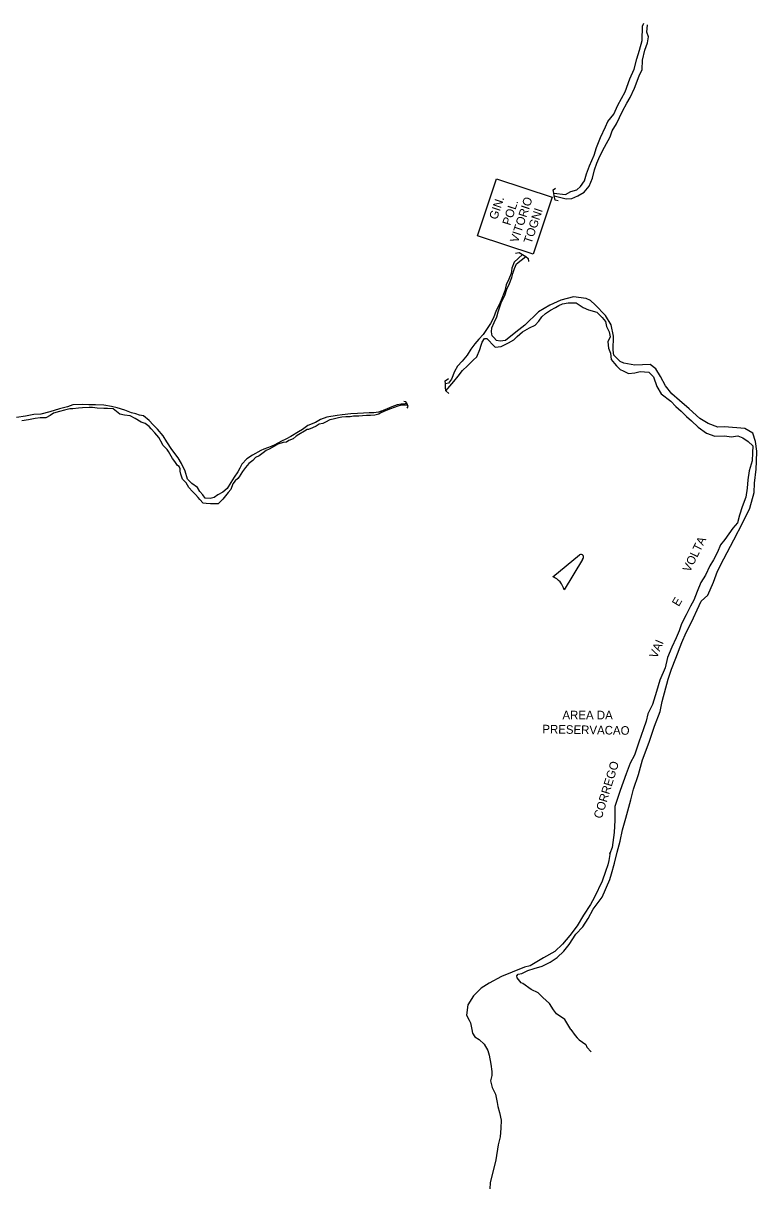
# Model space of a CAD drawing. Extents: x 325899 to 363134, y 7578590 to 7592502.
# Drawn here: x 337514 to 337857, y 7587928 to 7588472 of the extents above; entities that cross this region are included whole.
import ezdxf

# ---------------------------------------------------------------- set-up
doc = ezdxf.new("R2010")
doc.units = 0
for name, color, linetype in [('EDIFEXISTENT', 7, 'Continuous'), ('EDIFIDENTIF', 7, 'Continuous'), ('EDIFOBRAEXIS', 7, 'Continuous')]:
    doc.layers.add(name, color=color, linetype=linetype)

msp = doc.modelspace()

# ---------------------------------------------------------------- linework, layer by layer
at = {"layer": 'EDIFEXISTENT'}
for p, q in [((337726.34, 7588372.59), (337735.22, 7588399.29)), ((337735.22, 7588399.29), (337761.07, 7588390.69)), ((337761.07, 7588390.69), (337752.23, 7588364.13)), ((337761.63, 7588394.08), (337762.66, 7588394.92)), ((337761.9, 7588392.59), (337761.63, 7588394.08)), ((337762.11, 7588391.28), (337761.9, 7588392.59)), ((337762.58, 7588389.34), (337762.11, 7588391.28)), ((337763.93, 7588388.98), (337762.58, 7588389.34)), ((337752.23, 7588364.13), (337726.34, 7588372.59)), ((337744.09, 7588364.52), (337745.79, 7588364.89)), ((337745.79, 7588364.89), (337747.26, 7588363.97)), ((337747.26, 7588363.97), (337748.81, 7588362.98)), ((337748.81, 7588362.98), (337749.94, 7588362.11)), ((337749.94, 7588362.11), (337750.06, 7588360.67)), ((337711.25, 7588304.95), (337712.73, 7588306.02)), ((337711.29, 7588303.56), (337711.25, 7588304.95)), ((337711.39, 7588302.04), (337711.29, 7588303.56)), ((337711.57, 7588300.23), (337711.39, 7588302.04)), ((337712.85, 7588298.93), (337711.57, 7588300.23)), ((337692.89, 7588295.17), (337691.84, 7588295.27)), ((337693.29, 7588294.43), (337692.89, 7588295.17)), ((337693.59, 7588293.76), (337693.29, 7588294.43)), ((337693.39, 7588292.08), (337693.99, 7588292.9)), ((337693.99, 7588292.9), (337693.59, 7588293.76))]:
    msp.add_line(p, q, dxfattribs=at)
at = {"layer": 'EDIFOBRAEXIS'}
for points in [[(337761.9, 7588392.59), (337767.4, 7588391.97), (337769.77, 7588393.35), (337772.6, 7588394.14), (337774.28, 7588395.74), (337776.25, 7588398.33), (337777.15, 7588401.67), (337778.58, 7588405.27), (337780.69, 7588410.32), (337781.84, 7588413.87), (337783.63, 7588418.56), (337785.95, 7588423.57), (337787.04, 7588426.05), (337789.84, 7588429.54), (337791.81, 7588433.68), (337795.16, 7588439.82), (337797.44, 7588445.96), (337799.47, 7588450.46), (337800.7, 7588455.33), (337801.92, 7588459.3), (337803.1, 7588463.89), (337803.22, 7588470.64), (337803.96, 7588471.9)], [(337762.11, 7588391.28), (337767.6, 7588389.86), (337770.29, 7588390.13), (337773.15, 7588391.26), (337776.09, 7588393.1), (337778.47, 7588395.77), (337780.02, 7588399.52), (337780.96, 7588403.45), (337782.01, 7588406.53), (337783.39, 7588409.9), (337785.49, 7588414.02), (337788.22, 7588418.85), (337789.15, 7588421.73), (337791.12, 7588424.93), (337792.58, 7588427.92), (337793.96, 7588430.94), (337795.94, 7588434.65), (337797.48, 7588437.31), (337799.58, 7588441.55), (337801.77, 7588447.44), (337803.07, 7588450.38), (337803.37, 7588454.62), (337804.4, 7588459.36), (337805.63, 7588462.78), (337806.07, 7588465.55), (337805.31, 7588467.78), (337805.59, 7588471.18)], [(337747.26, 7588363.97), (337743.39, 7588360.3), (337742.35, 7588357.52), (337741.98, 7588355.12), (337740.9, 7588352.34), (337739.64, 7588349.76), (337739.09, 7588346.91), (337737.37, 7588342.54), (337736.21, 7588340.12), (337735, 7588337.74), (337733.74, 7588334.4), (337732.41, 7588331.71), (337730.46, 7588328.97), (337728.87, 7588326.51), (337726.89, 7588324.41), (337725.04, 7588322.27), (337723.19, 7588319.74), (337721.51, 7588316.87), (337719.08, 7588314.12), (337717, 7588311.81), (337715.51, 7588309.35), (337714.13, 7588305.75), (337712.81, 7588303.91), (337711.29, 7588303.56)], [(337769.87, 7588001.91), (337767.07, 7588006.59), (337763.23, 7588009.28), (337761.83, 7588011.12), (337759.94, 7588014.04), (337756.83, 7588016.97), (337754.67, 7588019.12), (337751.35, 7588020.68), (337747.45, 7588023.45), (337746.59, 7588023.84), (337744.75, 7588026.1), (337744.61, 7588026.99), (337745.32, 7588027.79), (337746.94, 7588028.06), (337749.81, 7588029.52), (337752.67, 7588030.45), (337756.41, 7588031.51), (337760.15, 7588033.44), (337763.42, 7588035.56), (337766.63, 7588038.48), (337769, 7588041.68), (337772.19, 7588046.42), (337775.52, 7588049.92), (337777.96, 7588053.86), (337780.32, 7588058.1), (337784.46, 7588063.82), (337787.98, 7588071.99), (337788.78, 7588074.75), (337790.17, 7588079.61), (337791.42, 7588084.78), (337792.8, 7588089.91), (337793.92, 7588095.15), (337795.55, 7588100.66), (337797.8, 7588109.17), (337799.14, 7588114.19), (337801.46, 7588121.07), (337803.35, 7588127.93), (337806.41, 7588136.22), (337808.86, 7588143.59), (337811.48, 7588150.51), (337812.54, 7588155.12), (337815.35, 7588165.54), (337816.79, 7588170.23), (337818.85, 7588175.41), (337821.68, 7588182.76), (337823.65, 7588187.41), (337826.15, 7588192.27), (337829.78, 7588199.98), (337830.69, 7588202), (337833.78, 7588204.86), (337836.42, 7588210.83), (337838.33, 7588215.99), (337841.2, 7588221.74), (337845.86, 7588230.74), (337850.07, 7588238.77), (337853.41, 7588245.49), (337855.37, 7588252.78), (337855.57, 7588257.2), (337856.35, 7588263.71), (337856.53, 7588267.32), (337856.59, 7588272.06), (337856.1, 7588276.6), (337854.73, 7588280.52), (337851.07, 7588282.71), (337841.51, 7588283.37), (337838.52, 7588283.31), (337833.93, 7588284.95), (337829.99, 7588287.28), (337825.05, 7588291.84), (337820.51, 7588295.67), (337817.06, 7588298.9), (337813.99, 7588302.64), (337811.65, 7588306.98), (337809.57, 7588310.53), (337806.83, 7588312.55), (337799.75, 7588312.2), (337794.63, 7588313.15), (337792.87, 7588313.94), (337789.84, 7588316.92), (337789.63, 7588319.31), (337789.75, 7588325.73), (337788.74, 7588331.08), (337786.04, 7588335.41), (337781.28, 7588340.35), (337779.09, 7588342.48), (337777.02, 7588343.42), (337771.1, 7588344.08), (337765.2, 7588342.58), (337760, 7588340.23), (337754.68, 7588337.21), (337748.42, 7588330.96), (337744.24, 7588327.7), (337739.42, 7588323.83), (337736.91, 7588323.47), (337735.18, 7588323.75), (337733.92, 7588325.13), (337733.12, 7588325.96), (337732.86, 7588327.86), (337733.02, 7588329.67), (337734, 7588332.22), (337735.26, 7588334.82), (337735.87, 7588337.09), (337737.26, 7588341.3), (337738.99, 7588344.83), (337739.94, 7588347.71), (337741.25, 7588350.37), (337742.31, 7588353.2), (337742.84, 7588355.01), (337743.55, 7588357.33), (337744.49, 7588359.55), (337748.81, 7588362.98)], [(337711.57, 7588300.23), (337715.24, 7588304.6), (337717.32, 7588307.04), (337719.34, 7588309.71), (337721.54, 7588311.92), (337724.28, 7588314.57), (337726.01, 7588316.17), (337727.34, 7588319.59), (337728, 7588321.52), (337728.38, 7588323.03), (337729.5, 7588324.69), (337730.57, 7588324.66), (337731.75, 7588323.66), (337733.09, 7588321.97), (337734.46, 7588320.64), (337737.27, 7588320.94), (337740.7, 7588322.71), (337743.2, 7588324.01), (337744.78, 7588325.58), (337747.26, 7588327.79), (337750.54, 7588329.74), (337753.14, 7588330.89), (337754.94, 7588332.72), (337756.29, 7588334.82), (337758.02, 7588336.39), (337760.36, 7588337.87), (337762.63, 7588339.22), (337764.27, 7588340.03), (337766.01, 7588340.96), (337768.54, 7588341.35), (337772.28, 7588341.3), (337775.58, 7588339.18), (337778.16, 7588338.02), (337781.96, 7588337.01), (337783.4, 7588335.53), (337784.48, 7588334.53), (337786.02, 7588332.69), (337786.56, 7588330.36), (337787.79, 7588327.87), (337788.2, 7588325.46), (337787.19, 7588323.09), (337787.35, 7588320.19), (337788.38, 7588317.77), (337788.72, 7588314.85), (337790.27, 7588312.94), (337791.12, 7588311.89), (337792.82, 7588310.26), (337794.27, 7588309.57), (337796.78, 7588308.28), (337799.69, 7588308.67), (337802.22, 7588309.32), (337806.32, 7588309.04), (337808.43, 7588306.76), (337810.01, 7588302.23), (337811.98, 7588298.83), (337816.5, 7588295.38), (337818.92, 7588292.98), (337821.41, 7588290.7), (337823.8, 7588288.32), (337826.11, 7588286.27), (337829.28, 7588283.26), (337833.22, 7588280.55), (337837.03, 7588279.02), (337841.8, 7588279.26), (337844.62, 7588278.81), (337847.82, 7588279.21), (337850.09, 7588278.28), (337852.55, 7588276.61), (337854.73, 7588274.53), (337854.65, 7588271.33), (337854.44, 7588267.49), (337853.03, 7588262.85), (337852.5, 7588258.71), (337852.17, 7588254.87), (337851.59, 7588250.62), (337849.82, 7588246), (337848.55, 7588242.12), (337847.61, 7588238.61), (337845.46, 7588236.07), (337841.77, 7588230.86), (337839.77, 7588228.37), (337838.27, 7588224.85), (337836.36, 7588221.27), (337834.72, 7588218.58), (337832.69, 7588214.14), (337830.53, 7588210.68), (337828.76, 7588206.54), (337827.26, 7588202.56), (337825.65, 7588199.67), (337823.62, 7588195.64), (337821.56, 7588191.47), (337820.34, 7588188.2), (337819.03, 7588184.89), (337817.03, 7588180.52), (337814.89, 7588175.77), (337813.81, 7588170.93), (337811.32, 7588165.06), (337809.79, 7588159.8), (337807.96, 7588153.69), (337805.86, 7588149.37), (337804.94, 7588145.95), (337803.74, 7588142.33), (337801.51, 7588136.23), (337799.61, 7588130.17), (337797.55, 7588126.43), (337795.67, 7588121.3), (337792.82, 7588113.67), (337790.33, 7588106.05), (337790.39, 7588099.78), (337790.03, 7588094.01), (337789.08, 7588087.01), (337788.03, 7588084.11), (337788.15, 7588084.61), (337787.51, 7588080.87), (337787.05, 7588078.89), (337786.1, 7588075.7), (337784.54, 7588071.24), (337780.85, 7588063.7), (337778.99, 7588060.35), (337775.76, 7588055.35), (337772.77, 7588050.41), (337769.3, 7588045.9), (337765.95, 7588041.84), (337762.32, 7588038.37), (337757.02, 7588035.51), (337750.88, 7588031.74), (337748.22, 7588031.15), (337742.43, 7588028.79), (337737.51, 7588026.77), (337731.76, 7588023.67), (337728.06, 7588021.21), (337724.35, 7588017.64), (337721.76, 7588013.46), (337721.16, 7588008.6), (337722.39, 7588006.26), (337722.96, 7588005.12), (337723.6, 7588001.91)], [(337681.39, 7588290.82), (337680.09, 7588290.34), (337677.88, 7588290.03), (337675.74, 7588289.91), (337673.08, 7588289.85), (337670.28, 7588289.68), (337667.15, 7588289.56), (337663.14, 7588289.03), (337660.83, 7588288.66), (337655.98, 7588287.9), (337652.98, 7588286.79), (337650.63, 7588285.51), (337647.15, 7588283.99), (337644.65, 7588282.2), (337642.8, 7588281.14), (337639.07, 7588278.99), (337636.76, 7588277.63), (337634.86, 7588276.78), (337631.74, 7588275.06), (337629.92, 7588274.31), (337626.49, 7588273.07), (337625.1, 7588272.33), (337621.32, 7588270.2), (337618.64, 7588268.48), (337616.21, 7588265.98), (337615.38, 7588264.09), (337614.35, 7588262.38), (337612.76, 7588259.88), (337611.12, 7588257.48), (337609.43, 7588254.58), (337607.41, 7588252.94), (337605.03, 7588251.63), (337603.41, 7588250.4), (337601.48, 7588250.01), (337599.21, 7588250.15), (337598.11, 7588251.67), (337596.71, 7588253.29), (337595.53, 7588255.06), (337592.87, 7588256.95), (337590.88, 7588259.03), (337589.84, 7588262.78), (337588.04, 7588266.36), (337586.5, 7588268.89), (337583.56, 7588272.89), (337581.25, 7588276.39), (337579.61, 7588279.28), (337576.9, 7588282.31), (337574.83, 7588284.31), (337572.96, 7588286.38), (337570.31, 7588288.58), (337568.5, 7588288.87), (337566.87, 7588289.48), (337564.81, 7588290.05), (337561.7, 7588291.28), (337558.16, 7588292.28), (337555.41, 7588292.97), (337551.9, 7588293.49), (337548.03, 7588293.64), (337544.86, 7588293.65), (337541.83, 7588293.89), (337537.43, 7588293.77), (337534.9, 7588292.79), (337531.11, 7588291.85), (337526.62, 7588290.5), (337522.53, 7588289.41), (337519.26, 7588289.24), (337515.22, 7588288.46), (337511.08, 7588287.72)], [(337681.39, 7588290.13), (337681.39, 7588290.13), (337680.2, 7588289.28), (337678.37, 7588288.81), (337676.39, 7588288.7), (337674.48, 7588288.76), (337672.65, 7588288.58), (337670.87, 7588288.49), (337668.43, 7588288.4), (337666.83, 7588288.16), (337664.82, 7588288.15), (337662.94, 7588287.96), (337661.44, 7588287.57), (337658.98, 7588286.98), (337657.38, 7588286.69), (337655.35, 7588285.61), (337654.01, 7588285.02), (337652.44, 7588284.73), (337650.97, 7588283.78), (337649.27, 7588282.91), (337647.39, 7588282.26), (337646.78, 7588282.16), (337645.46, 7588281.49), (337642.85, 7588279.87), (337641.71, 7588279.03), (337640.17, 7588277.85), (337638.22, 7588277), (337637.1, 7588276.23), (337635.6, 7588276.12), (337633.01, 7588275.37), (337631.49, 7588274.35), (337629.11, 7588272.99), (337627.69, 7588272.39), (337626.25, 7588271.32), (337624.4, 7588269.96), (337622.73, 7588269.06), (337621.44, 7588267.76), (337619.62, 7588266.25), (337617.92, 7588264.41), (337616.66, 7588262.62), (337615, 7588260.1), (337614.34, 7588259.36), (337613.15, 7588258.18), (337612.09, 7588256.88), (337611.17, 7588254.15), (337609.93, 7588252.75), (337608.72, 7588251.17), (337607.45, 7588249.71), (337605.25, 7588247.54), (337603.27, 7588247.47), (337601.67, 7588247.42), (337599.63, 7588247.68), (337598.21, 7588247.78), (337596.73, 7588249.5), (337595.88, 7588250.46), (337594.68, 7588251.85), (337593.2, 7588253.29), (337591.51, 7588255.11), (337590.23, 7588257.27), (337588.64, 7588259.06), (337587.74, 7588261.3), (337587.55, 7588262.72), (337587.55, 7588263.86), (337587.08, 7588264.85), (337586.32, 7588265.41), (337585.01, 7588267.28), (337583.86, 7588268.62), (337582.01, 7588271.97), (337581.45, 7588272.8), (337579.33, 7588274.8), (337579.3, 7588275.41), (337577.48, 7588278.53), (337575.64, 7588280.7), (337574, 7588282.55), (337572.98, 7588283.56), (337571.19, 7588284.97), (337569.28, 7588285.55), (337566.52, 7588287.31), (337564.2, 7588288.6), (337561.46, 7588288.84), (337559.29, 7588289.41), (337556.26, 7588291.78), (337553.56, 7588291.97), (337551.88, 7588291.96), (337548.7, 7588292.12), (337546.62, 7588292.44), (337544.94, 7588292.43), (337541.84, 7588292.31), (337539.96, 7588292.1), (337537.42, 7588291.91), (337535.99, 7588291.8), (337533.51, 7588291.2), (337531.12, 7588290.53), (337528.41, 7588289.75), (337526.76, 7588288.8), (337524.73, 7588287.65), (337522.11, 7588287.58), (337519.78, 7588287.31), (337516.75, 7588286.69), (337513.53, 7588286.26)], [(337681.39, 7588290.82), (337686.5, 7588292.95), (337688.92, 7588293.87), (337690.63, 7588294.22), (337692.54, 7588294.35), (337693.29, 7588294.43)], [(337681.39, 7588290.13), (337683.78, 7588291.29), (337685.9, 7588291.95), (337689.18, 7588293.29), (337690.76, 7588293.64), (337692.65, 7588293.79), (337693.59, 7588293.76)], [(337761.48, 7588213.46), (337773.86, 7588223.7)], [(337775.34, 7588221.51), (337766.69, 7588207.26)], [(337723.6, 7588001.91), (337723.88, 7588000.33), (337725.03, 7587998.48), (337726.99, 7587997.29), (337729.42, 7587995.16), (337731.05, 7587992.18), (337731.68, 7587990.03), (337732.47, 7587985.8), (337732.98, 7587982.36), (337733.02, 7587980.51), (337732.28, 7587977.94), (337733.12, 7587974.91), (337734.74, 7587971.75), (337735.46, 7587967.95), (337735.83, 7587966.08), (337736.49, 7587963.27), (337737.35, 7587959.7), (337737.15, 7587955.82), (337736.93, 7587951.92), (337735.92, 7587948.16), (337734.84, 7587941.07), (337732.14, 7587930.4), (337732.11, 7587927.54)], [(337769.87, 7588001.91), (337771.91, 7587999.23), (337772.78, 7587998.15), (337773.75, 7587997.12), (337776.79, 7587995.01), (337777.36, 7587993.75), (337779.38, 7587991.51)]]:
    msp.add_lwpolyline(points, dxfattribs=at)
for centre, radius, start, end in [((337774.48, 7588222.53), 1.33, 310.4106, 117.5493), ((337757.93, 7588205.2), 8.99, 13.258, 66.792)]:
    msp.add_arc(centre, radius, start, end, dxfattribs=at)

# ---------------------------------------------------------------- texts
at = {"layer": 'EDIFIDENTIF'}
for s, rotation, p in [('VITORIO', 71.5947, (337745.1, 7588369.11)), ('GIN.', 71.5947, (337735.35, 7588379.93)), ('POL.', 71.5947, (337741.54, 7588377.21)), ('TOGNI', 71.5947, (337751.43, 7588368.69)), ('VOLTA', 63.5711, (337825.35, 7588215.24)), ('E', 59.2542, (337820.21, 7588199.23)), ('VAI', 67.134, (337809.96, 7588174.98)), ('AREA DA', 359.9351, (337765.92, 7588146.85)), ('PRESERVACAO', 359.0044, (337756.5, 7588140.3)), ('CORREGO', 72.7816, (337784.2, 7588100.15))]:
    msp.add_text(s, height=4, rotation=rotation, dxfattribs=at).set_placement(p)

doc.saveas('drawing.dxf')
